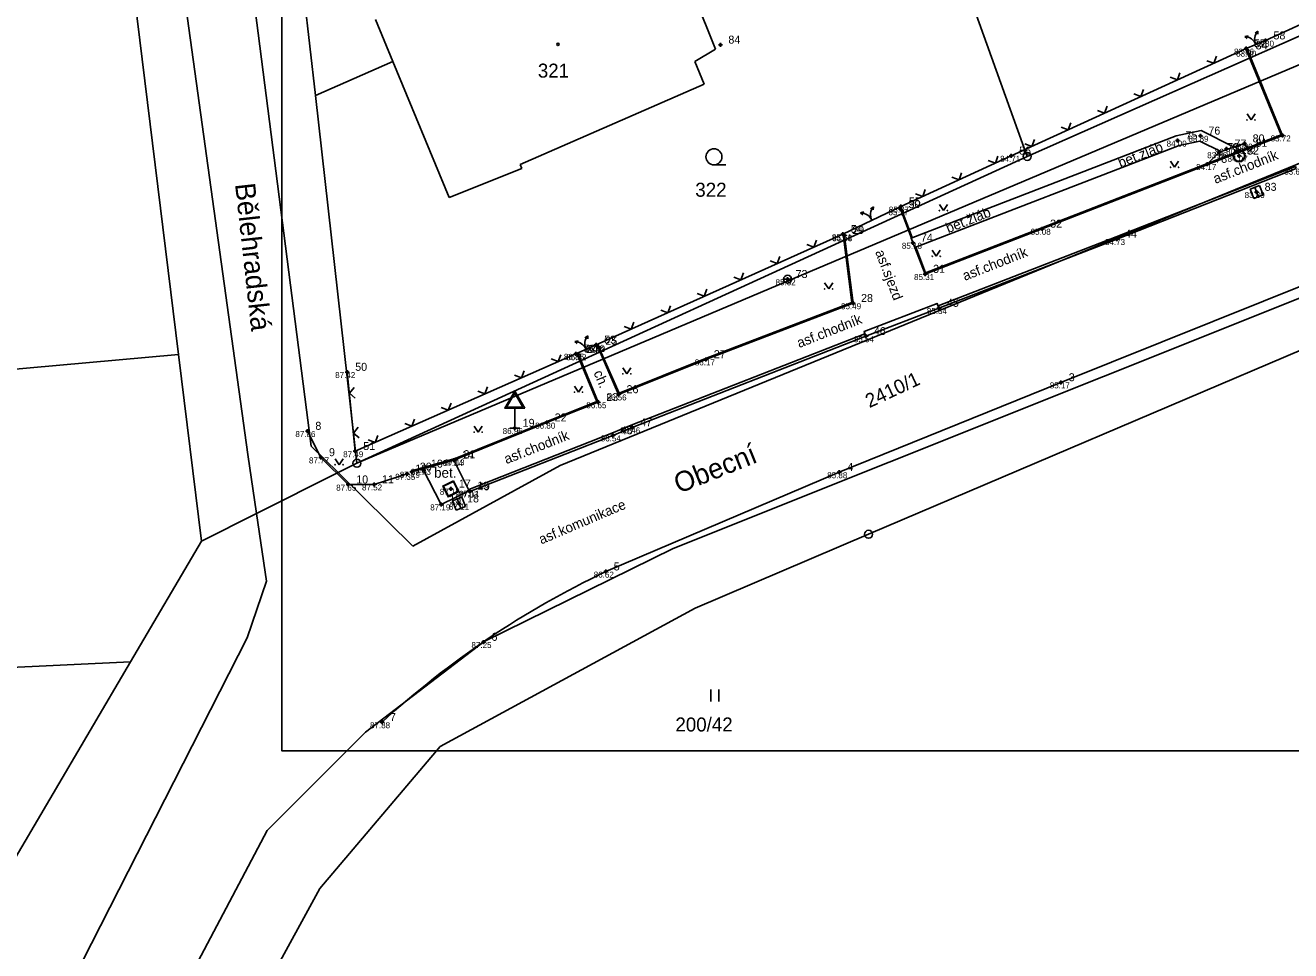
# Model space of a CAD drawing. Extents: x -454285 to -453563, y -1108687 to -1108249.
# Drawn here: x -454141.3 to -454078.1, y -1108574.8 to -1108528.5 of the extents above; entities that cross this region are included whole.
import ezdxf

# ---------------------------------------------------------------- set-up
doc = ezdxf.new("R2010")
doc.units = 0
for name, color, linetype in [('1', 7, 'Continuous'), ('14', 7, 'Continuous'), ('15', 7, 'Continuous'), ('16', 7, 'Continuous'), ('2', 7, 'Continuous'), ('23', 7, 'Continuous'), ('25', 7, 'Continuous'), ('28', 7, 'Continuous'), ('38', 7, 'Continuous'), ('bet.žláb', 7, 'Continuous'), ('beton', 7, 'Continuous'), ('BODY_T1_2018', 7, 'Continuous'), ('CISLA_T1_2018', 7, 'Continuous'), ('dopravní značka', 7, 'Continuous'), ('obrubník', 7, 'Continuous'), ('okraj asf.komunikace', 7, 'Continuous'), ('oplocení', 7, 'Continuous'), ('rámy', 7, 'Continuous'), ('sloup', 7, 'Continuous'), ('T', 7, 'Continuous'), ('uliční vpusť', 7, 'Continuous'), ('VYSKY_T1_2018', 7, 'Continuous'), ('zeleň', 7, 'Continuous'), ('šachtice', 7, 'Continuous')]:
    doc.layers.add(name, color=color, linetype=linetype)

# ---------------------------------------------------------------- blocks, each defined once
blk = doc.blocks.new('Z402')
for start, end in [(0, 180), (180, 0)]:
    blk.add_arc((0, 0), 0.15, start, end)
blk = doc.blocks.new('Z105')
for radius in [0.5, 0.01]:
    blk.add_circle((0, 0), radius)
blk = doc.blocks.new('Z3040')
blk.add_line((1.5, 0), (0, 0))
blk.add_circle((0, 1), 1)
blk = doc.blocks.new('PLOT05')
for q in [(-0.265, 0.265), (0.265, 0.265)]:
    blk.add_line((0, 0), q)
blk = doc.blocks.new('BRANKA')
for p, q in [((-0.351, 0.589), (-0.179, 0.552)), ((-0.351, 0.589), (-0.284, 0.449)), ((0.361, 0.583), (0.188, 0.549)), ((0.361, 0.583), (0.291, 0.445))]:
    blk.add_line(p, q)
for centre, start, end in [((-0.618, 0.03), 357.17506, 64.46884), ((0.619, 0.02), 114.58945, 181.88322)]:
    blk.add_arc(centre, 0.619, start, end)
blk = doc.blocks.new('PARK')
for p, q in [((0, 0), (-1, 1.5)), ((1, 1.5), (0, 0))]:
    blk.add_line(p, q)
for centre, start, end in [((-1, 0), 0, 180), ((1, 0), 0, 180), ((1, 0), 180, 0), ((-1, 0), 180, 0)]:
    blk.add_arc(centre, 0.05, start, end)
blk = doc.blocks.new('EL.SLOUP')
blk.add_line((0.4, 0), (-0.4, 0))
blk.add_line((0.4, 0), (-0.4, 0))
blk.add_lwpolyline([(0.4, 0), (-0.4, 0)])
blk.add_lwpolyline([(0.4, 0), (-0.4, 0)])
blk.add_circle((0, 0), 0.4)
blk.add_circle((0, 0), 0.4)
for start, end in [(270, 0), (270, 0), (180, 270), (180, 270)]:
    blk.add_arc((0, 0), 0.4, start, end)
blk = doc.blocks.new('šachtice_kruh_velká')
for radius in [0.5, 0.495, 0.495, 0.455, 0.455, 0.45]:
    blk.add_circle((0, 0), radius)
blk = doc.blocks.new('vpusť')
for p, q in [((0.25, 0.25), (-0.25, 0.25)), ((-0.25, 0.25), (-0.25, -0.25)), ((-0.25, 0), (0.25, 0)), ((0.25, -0.25), (0.25, 0.25)), ((-0.25, -0.25), (0.25, -0.25))]:
    blk.add_line(p, q)
blk = doc.blocks.new('šachtice_hranatá_velká')
for p, q in [((-0.5, 0.5), (0.5, 0.5)), ((-0.5, -0.5), (-0.5, 0.5)), ((0.45, 0.45), (-0.45, 0.45)), ((-0.45, 0.45), (-0.45, -0.45)), ((0.45, -0.45), (0.45, 0.45)), ((0.5, 0.5), (0.5, -0.5)), ((0.5, -0.5), (-0.5, -0.5)), ((-0.45, -0.45), (0.45, -0.45))]:
    blk.add_line(p, q)
for points in [[(-0.5, 0.5), (0.5, 0.5), (0.5, -0.5), (-0.5, -0.5)], [(-0.45, 0.45), (0.45, 0.45), (0.45, -0.45), (-0.45, -0.45)]]:
    blk.add_lwpolyline(points, close=True)
blk = doc.blocks.new('Dzdoprzn_trouhelnik')
blk.add_line((0.5, 0), (-0.5, 0))
for points in [[(1, 2), (0.01, 3.68), (-0.99, 2)], [(0.82, 2.1), (0.01, 3.49), (-0.81, 2.1)]]:
    blk.add_lwpolyline(points, close=True)
blk.add_lwpolyline([(0, 0), (0, 2)])
blk = doc.blocks.new('POINT_DISPLAY')
for p, q in [((-0.1, 0), (0.1, 0)), ((0, -0.1), (0, 0.1))]:
    blk.add_line(p, q)
blk.add_circle((0, 0), 0.05)
blk = doc.blocks.new('t1_2018')
at = {"layer": 'BODY_T1_2018'}
for p in [(-454106.59, -1108529.5), (-454079.35, -1108529.29), (-454080.32, -1108529.69), (-454080.24, -1108529.79), (-454082.6, -1108534.05), (-454078.49, -1108534.03), (-454083.74, -1108534.29), (-454081.3, -1108534.7), (-454080.39, -1108534.44), (-454080.25, -1108534.66), (-454092.06, -1108535.05), (-454081.66, -1108534.87), (-454080.67, -1108535.05), (-454082.26, -1108535.46), (-454079.79, -1108536.86), (-454097.59, -1108537.72), (-454097.57, -1108537.59), (-454100.47, -1108538.97), (-454100.4, -1108539.02), (-454090.51, -1108538.7), (-454096.97, -1108539.4), (-454086.77, -1108539.21), (-454096.36, -1108540.96), (-454103.23, -1108541.22), (-454099.96, -1108542.42), (-454095.67, -1108542.66), (-454099.32, -1108544.07), (-454112.8, -1108544.5), (-454112.74, -1108544.56), (-454113.81, -1108544.95), (-454113.69, -1108544.97), (-454107.32, -1108545.23), (-454125.24, -1108545.86), (-454089.58, -1108546.38), (-454111.68, -1108546.98), (-454112.69, -1108547.37), (-454115.27, -1108548.39), (-454127.23, -1108548.81), (-454116.87, -1108548.66), (-454111.97, -1108549.03), (-454111, -1108548.63), (-454124.84, -1108549.82), (-454126.55, -1108550.13), (-454119.91, -1108550.26), (-454119.83, -1108550.23), (-454122.24, -1108550.95), (-454122.01, -1108550.85), (-454121.46, -1108550.7), (-454100.65, -1108550.87), (-454125.19, -1108551.49), (-454123.9, -1108551.48), (-454120.06, -1108551.7), (-454119.14, -1108551.8), (-454119.11, -1108551.84), (-454120.54, -1108552.48), (-454119.65, -1108552.44), (-454112.32, -1108555.84), (-454118.43, -1108559.36), (-454123.5, -1108563.37)]:
    blk.add_blockref('POINT_DISPLAY', p, dxfattribs=at)
at = {"layer": 'CISLA_T1_2018'}
for s, p in [('58', (-454078.95, -1108529.23)), ('84', (-454106.19, -1108529.44)), ('57', (-454079.92, -1108529.63)), ('34', (-454079.84, -1108529.73)), ('75', (-454083.34, -1108534.23)), ('76', (-454082.2, -1108533.99)), ('56', (-454091.66, -1108534.99)), ('79', (-454081.26, -1108534.81)), ('77', (-454080.9, -1108534.64)), ('82', (-454080.27, -1108534.99)), ('80', (-454079.99, -1108534.38)), ('81', (-454079.85, -1108534.6)), ('78', (-454081.86, -1108535.4)), ('83', (-454079.39, -1108536.8)), ('55', (-454097.17, -1108537.53)), ('30', (-454097.19, -1108537.66)), ('32', (-454090.11, -1108538.64)), ('54', (-454100.07, -1108538.91)), ('29', (-454100, -1108538.96)), ('74', (-454096.57, -1108539.34)), ('44', (-454086.37, -1108539.15)), ('73', (-454102.83, -1108541.16)), ('31', (-454095.96, -1108540.9)), ('28', (-454099.56, -1108542.36)), ('45', (-454095.27, -1108542.6)), ('53', (-454112.4, -1108544.44)), ('46', (-454098.92, -1108544.01)), ('52', (-454113.41, -1108544.89)), ('24', (-454113.29, -1108544.91)), ('25', (-454112.34, -1108544.5)), ('27', (-454106.92, -1108545.17)), ('50', (-454124.84, -1108545.8)), ('3', (-454089.18, -1108546.32)), ('26', (-454111.28, -1108546.92)), ('23', (-454112.29, -1108547.31)), ('8', (-454126.83, -1108548.75)), ('19', (-454116.47, -1108548.6)), ('22', (-454114.87, -1108548.33)), ('47', (-454110.6, -1108548.57)), ('48', (-454111.57, -1108548.97)), ('9', (-454126.15, -1108550.07)), ('51', (-454124.44, -1108549.76)), ('21', (-454119.43, -1108550.17)), ('20', (-454121.61, -1108550.79)), ('16', (-454121.06, -1108550.64)), ('14', (-454119.51, -1108550.2)), ('4', (-454100.25, -1108550.81)), ('10', (-454124.79, -1108551.43)), ('11', (-454123.5, -1108551.42)), ('12', (-454121.84, -1108550.89)), ('17', (-454119.66, -1108551.64)), ('13', (-454118.74, -1108551.74)), ('49', (-454118.71, -1108551.78)), ('15', (-454120.14, -1108552.42)), ('18', (-454119.25, -1108552.38)), ('5', (-454111.92, -1108555.78)), ('6', (-454118.03, -1108559.3)), ('7', (-454123.1, -1108563.31))]:
    blk.add_text(s, height=0.4, dxfattribs=at).set_placement(p)
at = {"layer": 'VYSKY_T1_2018'}
for s, p in [('83.80', (-454079.925, -1108529.59)), ('83.86', (-454080.92, -1108529.99)), ('83.80', (-454080.815, -1108530.09)), ('84.00', (-454084.29, -1108534.59)), ('83.89', (-454083.2, -1108534.35)), ('83.89', (-454080.99, -1108534.74)), ('83.72', (-454079.09, -1108534.33)), ('84.71', (-454092.61, -1108535.35)), ('83.86', (-454082.26, -1108535.17)), ('83.60', (-454081.875, -1108535)), ('84.07', (-454081.245, -1108535.35)), ('83.92', (-454080.85, -1108534.96)), ('84.17', (-454082.81, -1108535.76)), ('83.65', (-454078.41, -1108535.99)), ('83.89', (-454080.39, -1108537.16)), ('85.37', (-454098.19, -1108538.02)), ('85.37', (-454098.17, -1108537.89)), ('85.61', (-454101.02, -1108539.27)), ('85.58', (-454101, -1108539.32)), ('85.08', (-454091.085, -1108539)), ('85.18', (-454097.52, -1108539.7)), ('84.73', (-454087.37, -1108539.51)), ('85.82', (-454103.83, -1108541.52)), ('85.31', (-454096.91, -1108541.26)), ('85.49', (-454100.56, -1108542.72)), ('85.34', (-454096.27, -1108542.96)), ('85.54', (-454099.92, -1108544.37)), ('86.76', (-454113.4, -1108544.8)), ('86.79', (-454113.34, -1108544.86)), ('86.85', (-454114.41, -1108545.25)), ('86.82', (-454114.29, -1108545.27)), ('86.17', (-454107.87, -1108545.53)), ('87.42', (-454125.84, -1108546.16)), ('85.17', (-454090.13, -1108546.68)), ('86.56', (-454112.28, -1108547.28)), ('86.65', (-454113.29, -1108547.67)), ('86.80', (-454115.845, -1108548.69)), ('87.86', (-454127.83, -1108549.11)), ('86.96', (-454117.47, -1108548.96)), ('86.54', (-454112.57, -1108549.33)), ('86.46', (-454111.6, -1108548.93)), ('87.77', (-454127.15, -1108550.43)), ('87.49', (-454125.44, -1108550.12)), ('87.14', (-454120.46, -1108550.56)), ('87.13', (-454120.38, -1108550.53)), ('87.35', (-454122.84, -1108551.25)), ('87.29', (-454122.61, -1108551.15)), ('87.23', (-454122.06, -1108551)), ('85.88', (-454101.25, -1108551.17)), ('87.65', (-454125.79, -1108551.79)), ('87.52', (-454124.5, -1108551.78)), ('87.15', (-454120.61, -1108552)), ('87.07', (-454119.685, -1108552.14)), ('87.11', (-454119.64, -1108552.1)), ('87.19', (-454121.09, -1108552.78)), ('87.11', (-454120.15, -1108552.74)), ('86.62', (-454112.92, -1108556.14)), ('87.25', (-454119.03, -1108559.66)), ('87.88', (-454124.1, -1108563.67))]:
    blk.add_text(s, height=0.3, dxfattribs=at).set_placement(p)
blk = doc.blocks.new('Z3060')
for p, q in [((-0.5, 1.5), (-0.5, 0)), ((0.5, 1.5), (0.5, 0))]:
    blk.add_line(p, q)

msp = doc.modelspace()

# ---------------------------------------------------------------- linework, layer by layer
at = {"layer": '1'}
for p, q in [((-453969.347, -1108484.681), (-454124.757, -1108550.421)), ((-454103.897, -1108499.911), (-454091.257, -1108535.081)), ((-453988.627, -1108506.811), (-454099.187, -1108553.971)), ((-454133.677, -1108544.981), (-454137.067, -1108517.391)), ((-454126.827, -1108532.041), (-454128.187, -1108520.021)), ((-454106.827, -1108529.711), (-454109.107, -1108524.021)), ((-454091.257, -1108535.081), (-454066.217, -1108523.991)), ((-454107.867, -1108530.341), (-454106.827, -1108529.711)), ((-454126.827, -1108532.041), (-454122.957, -1108530.341)), ((-454122.957, -1108530.341), (-454120.137, -1108537.131)), ((-454107.397, -1108531.471), (-454107.867, -1108530.341)), ((-454124.757, -1108550.421), (-454126.827, -1108532.041)), ((-454116.597, -1108535.481), (-454107.397, -1108531.471)), ((-454091.257, -1108535.081), (-454124.757, -1108550.421)), ((-454120.137, -1108537.131), (-454116.517, -1108535.681)), ((-454116.517, -1108535.681), (-454116.597, -1108535.481)), ((-454169.067, -1108548.201), (-454133.677, -1108544.981)), ((-454133.677, -1108544.981), (-454132.527, -1108554.311)), ((-454129.767, -1108552.931), (-454125.697, -1108550.891)), ((-454125.697, -1108550.891), (-454124.757, -1108550.421)), ((-454132.527, -1108554.311), (-454129.767, -1108552.931)), ((-454107.857, -1108557.671), (-454099.187, -1108553.971)), ((-454136.077, -1108560.351), (-454132.527, -1108554.311)), ((-454107.857, -1108557.671), (-454120.587, -1108564.591)), ((-454148.607, -1108560.941), (-454136.077, -1108560.351)), ((-454136.077, -1108560.351), (-454142.117, -1108570.651)), ((-454120.587, -1108564.591), (-454126.607, -1108571.681)), ((-454126.607, -1108571.681), (-454130.667, -1108579.121))]:
    msp.add_line(p, q, dxfattribs=at)
at = {"layer": '2'}
for p, q in [((-454136.867, -1108472.781), (-454127.047, -1108549.571)), ((-454130.207, -1108549.991), (-454140.737, -1108473.691)), ((-454123.827, -1108528.241), (-454122.957, -1108530.341)), ((-454114.597, -1108550.531), (-454063.887, -1108529.801)), ((-454060.357, -1108535.251), (-454108.957, -1108554.681)), ((-454127.047, -1108549.571), (-454125.697, -1108550.891)), ((-454130.207, -1108549.991), (-454129.767, -1108552.931)), ((-454125.697, -1108550.891), (-454121.957, -1108554.561)), ((-454121.957, -1108554.561), (-454114.597, -1108550.531)), ((-454129.767, -1108552.931), (-454129.267, -1108556.311)), ((-454108.957, -1108554.681), (-454118.397, -1108559.331)), ((-454130.237, -1108559.151), (-454129.267, -1108556.311)), ((-454160.757, -1108619.101), (-454130.237, -1108559.151)), ((-454118.397, -1108559.331), (-454124.317, -1108563.861)), ((-454124.317, -1108563.861), (-454129.237, -1108568.791)), ((-454129.237, -1108568.791), (-454133.447, -1108576.741))]:
    msp.add_line(p, q, dxfattribs=at)
at = {"layer": 'bet.žláb'}
msp.add_lwpolyline([(-454080.909, -1108534.616), (-454082.566, -1108533.787), (-454083.811, -1108534.05), (-454097.06, -1108539.167), (-454096.88, -1108539.633), (-454083.669, -1108534.53), (-454082.634, -1108534.313), (-454081.576, -1108534.842)], dxfattribs=at)
at = {"layer": 'beton'}
msp.add_lwpolyline([(-454082.228, -1108535.429), (-454081.66, -1108534.87), (-454080.39, -1108534.44), (-454080.25, -1108534.66)], dxfattribs=at)
msp.add_lwpolyline([(-454121.46, -1108550.7), (-454120.54, -1108552.48), (-454119.14, -1108551.8), (-454119.91, -1108550.26)], close=True, dxfattribs=at)
at = {"layer": 'obrubník'}
for points in [[(-454080.287, -1108529.676), (-454078.49, -1108534.03), (-454090.51, -1108538.7), (-454096.36, -1108540.96), (-454096.866, -1108539.628), (-454096.819, -1108539.61), (-454096.331, -1108540.895), (-454090.528, -1108538.653), (-454078.556, -1108534.002), (-454080.333, -1108529.696)], [(-454097.583, -1108537.596), (-454096.997, -1108539.142), (-454097.043, -1108539.16), (-454097.629, -1108537.618)], [(-454112.772, -1108544.487), (-454111.68, -1108546.98), (-454107.32, -1108545.23), (-454099.96, -1108542.42), (-454100.41, -1108538.942)], [(-454112.726, -1108544.467), (-454111.654, -1108546.916), (-454107.338, -1108545.183), (-454100.015, -1108542.387), (-454100.458, -1108538.964)], [(-454113.762, -1108544.928), (-454112.756, -1108547.342), (-454115.289, -1108548.344), (-454119.846, -1108550.183), (-454122.024, -1108550.802), (-454122.01, -1108550.85), (-454119.83, -1108550.23), (-454115.27, -1108548.39), (-454112.69, -1108547.37), (-454113.716, -1108544.908)]]:
    msp.add_lwpolyline(points, dxfattribs=at)
for points in [[(-454077.81, -1108535.69), (-454086.77, -1108539.21), (-454095.67, -1108542.66), (-454095.713, -1108542.548), (-454086.814, -1108539.098), (-454077.855, -1108535.579)], [(-454099.32, -1108544.07), (-454095.67, -1108542.66), (-454095.76, -1108542.427), (-454099.41, -1108543.837)], [(-454099.363, -1108543.958), (-454099.32, -1108544.07), (-454111, -1108548.63), (-454111.97, -1108549.03), (-454119.11, -1108551.84), (-454119.154, -1108551.728), (-454112.015, -1108548.919), (-454111.045, -1108548.519)]]:
    msp.add_lwpolyline(points, close=True, dxfattribs=at)
at = {"layer": 'okraj asf.komunikace'}
for points in [[(-454112.32, -1108555.84), (-454100.65, -1108550.87), (-454089.58, -1108546.38), (-454076.91, -1108541.3), (-454064.18, -1108535.73), (-454053.87, -1108531.55), (-454045.79, -1108528.05), (-454030.23, -1108521.06), (-454017.66, -1108515.77), (-454004.84, -1108509.89), (-453993.47, -1108504.93), (-453991.99, -1108504.49), (-453990.15, -1108504.23), (-453988.99, -1108504.84), (-453987.94, -1108505.97), (-453986.82, -1108510.84)], [(-454127.23, -1108548.81), (-454126.55, -1108550.13), (-454125.19, -1108551.49), (-454123.9, -1108551.48), (-454122.24, -1108550.95)]]:
    msp.add_lwpolyline(points, dxfattribs=at)
msp.add_arc((-454092.679, -1108597.066), 45.666, 115.4741, 132.44834, dxfattribs=at)
at = {"layer": 'oplocení'}
msp.add_lwpolyline([(-454125.24, -1108545.86), (-454124.84, -1108549.82), (-454113.81, -1108544.95), (-454112.8, -1108544.5), (-454100.47, -1108538.97), (-454097.57, -1108537.59), (-454092.06, -1108535.05), (-454080.32, -1108529.69), (-454079.35, -1108529.29), (-454075.63, -1108527.58), (-454069.87, -1108524.95), (-454066.24, -1108523.74), (-454058.33, -1108520.39), (-454057.22, -1108519.88), (-454050.24, -1108516.86), (-454045.48, -1108514.77), (-454020.87, -1108504.33), (-454019.7, -1108503.81), (-454015.75, -1108502.12)], dxfattribs=at)
at = {"layer": 'rámy'}
msp.add_lwpolyline([(-454128.499, -1108504.754), (-454029.331, -1108504.754), (-454029.331, -1108564.805), (-454128.499, -1108564.805)], close=True, dxfattribs=at)

# ---------------------------------------------------------------- block references
msp.add_blockref('t1_2018', (0, 0))
at = {"layer": '23', "xscale": 0.4, "yscale": 0.4000000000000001}
for name, p in [('Z3040', (-454106.91, -1108535.501)), ('Z3060', (-454106.866, -1108562.339))]:
    msp.add_blockref(name, p, dxfattribs=at)
at = {"layer": '25', "xscale": 0.4, "yscale": 0.4000000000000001}
msp.add_blockref('Z402', (-454114.706, -1108529.482), dxfattribs=at)
at = {"layer": '28', "xscale": 0.4, "yscale": 0.4000000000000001}
for p in [(-454091.257, -1108535.081), (-454124.757, -1108550.421), (-454099.187, -1108553.971)]:
    msp.add_blockref('Z105', p, dxfattribs=at)
at = {"layer": 'dopravní značka', "xscale": 0.5, "yscale": 0.5}
msp.add_blockref('Dzdoprzn_trouhelnik', (-454116.87, -1108548.66), dxfattribs=at)
at = {"layer": 'oplocení'}
for name, p, rotation in [('BRANKA', (-454079.835, -1108529.49), 22.4098373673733), ('PLOT05', (-454081.933, -1108530.426), 24.53948440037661), ('PLOT05', (-454083.752, -1108531.257), 24.53948440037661), ('PLOT05', (-454085.572, -1108532.088), 24.53948440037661), ('PLOT05', (-454087.391, -1108532.918), 24.53948440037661), ('PLOT05', (-454089.21, -1108533.749), 24.53948440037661), ('PLOT05', (-454091.03, -1108534.58), 24.53948440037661), ('PLOT05', (-454092.848, -1108535.413), 24.74875826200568), ('PLOT05', (-454094.664, -1108536.25), 24.74875826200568), ('PLOT05', (-454096.48, -1108537.088), 24.74875826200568), ('BRANKA', (-454099.02, -1108538.28), 25.448004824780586), ('PLOT05', (-454101.919, -1108539.62), 24.156215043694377), ('PLOT05', (-454103.744, -1108540.438), 24.156215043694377), ('PLOT05', (-454105.569, -1108541.257), 24.156215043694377), ('PLOT05', (-454107.394, -1108542.075), 24.156215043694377), ('PLOT05', (-454109.219, -1108542.894), 24.156215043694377), ('PLOT05', (-454111.044, -1108543.712), 24.156215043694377), ('BRANKA', (-454113.305, -1108544.725), 24.015102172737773), ('PLOT05', (-454114.697, -1108545.342), 23.82256692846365), ('PLOT05', (-454116.526, -1108546.149), 23.82256692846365), ('PLOT05', (-454118.356, -1108546.957), 23.82256692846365), ('PLOT05', (-454125.133, -1108546.923), -84.23211110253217), ('PLOT05', (-454120.186, -1108547.765), 23.82256692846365), ('PLOT05', (-454122.015, -1108548.573), 23.82256692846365), ('PLOT05', (-454124.932, -1108548.913), -84.23211110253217), ('PLOT05', (-454123.845, -1108549.381), 23.82256692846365)]:
    msp.add_blockref(name, p, dxfattribs=dict(at, rotation=rotation))
at = {"layer": 'sloup', "xscale": 0.5, "yscale": 0.5}
msp.add_blockref('EL.SLOUP', (-454103.23, -1108541.22), dxfattribs=at)
at = {"layer": 'uliční vpusť'}
for p, rotation in [((-454079.79, -1108536.86), 111.44773632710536), ((-454119.65, -1108552.44), 111.48248661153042)]:
    msp.add_blockref('vpusť', p, dxfattribs=dict(at, rotation=rotation))
at = {"layer": 'zeleň', "xscale": 0.2, "yscale": 0.20000000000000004}
for p in [(-454080.071, -1108533.255), (-454083.891, -1108535.622), (-454095.446, -1108537.789), (-454095.804, -1108540.07), (-454101.178, -1108541.705), (-454111.268, -1108545.95), (-454113.687, -1108546.868), (-454118.691, -1108548.867), (-454125.645, -1108550.496)]:
    msp.add_blockref('PARK', p, dxfattribs=at)
at = {"layer": 'šachtice', "xscale": 0.6, "yscale": 0.6}
msp.add_blockref('šachtice_kruh_velká', (-454080.67, -1108535.05), dxfattribs=at)
at = {"layer": 'šachtice', "xscale": 0.6, "yscale": 0.5999999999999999, "rotation": -64.0934919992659}
msp.add_blockref('šachtice_hranatá_velká', (-454120.06, -1108551.7), dxfattribs=at)

# ---------------------------------------------------------------- texts
at = {"layer": '14'}
msp.add_text('322', height=0.7, dxfattribs=at).set_placement((-454107.843, -1108537.097))
at = {"layer": '15'}
msp.add_text('321', height=0.7, dxfattribs=at).set_placement((-454115.713, -1108531.141))
at = {"layer": '16'}
msp.add_text('2410/1', height=0.7, rotation=25.1016, dxfattribs=at).set_placement((-454099.14, -1108547.669))
msp.add_text('200/42', height=0.7, dxfattribs=at).set_placement((-454108.838, -1108563.833))
at = {"layer": '38'}
for s, rotation, p in [('Bělehradská', 276.336, (-454130.847, -1108536.461)), ('Obecní', 21.834, (-454108.667, -1108551.951))]:
    msp.add_text(s, height=1, rotation=rotation, dxfattribs=at).set_placement(p)
at = {"layer": 'T'}
for s, rotation, p in [('bet.žláb', 21.48249, (-454086.597, -1108535.649)), ('asf.chodník', 21.48249, (-454081.847, -1108536.456)), ('bet.žláb', 21.48249, (-454095.204, -1108538.919)), ('asf.chodník', 21.48249, (-454094.371, -1108541.306)), ('asf.sjezd', 290.78825, (-454098.86, -1108539.857)), ('asf.chodník', 21.48249, (-454102.649, -1108544.663)), ('ch.', 292.61986, (-454112.939, -1108545.89)), ('asf.chodník', 21.48249, (-454117.283, -1108550.47)), ('asf.komunikace', 23.0681, (-454115.536, -1108554.486))]:
    msp.add_text(s, height=0.5, rotation=rotation, dxfattribs=at).set_placement(p)
msp.add_text('bet.', height=0.5, dxfattribs=at).set_placement((-454120.897, -1108551.145))

doc.saveas('drawing.dxf')
